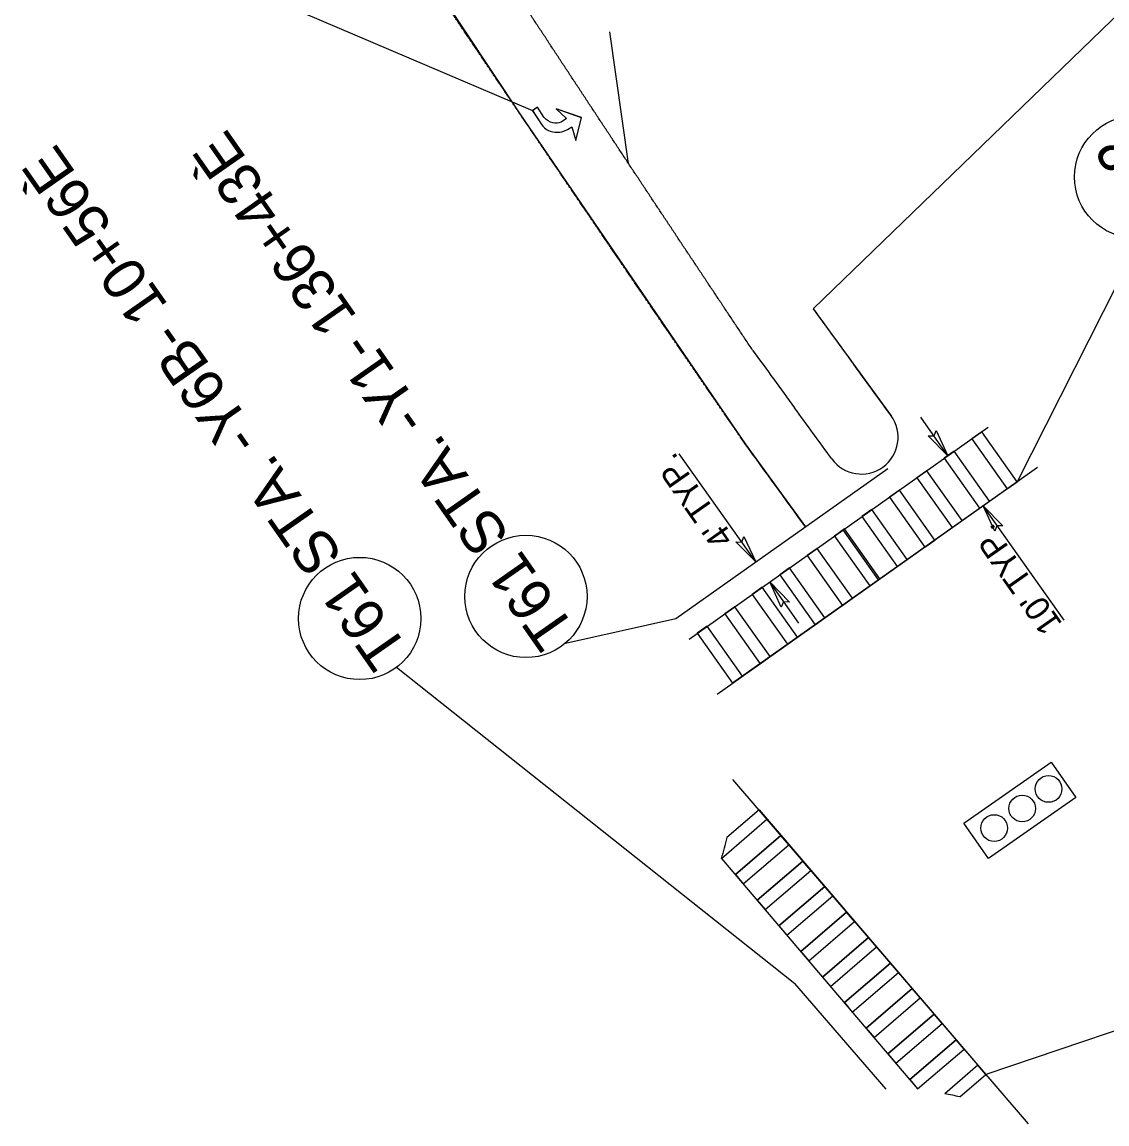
# Model space of a CAD drawing. Extents: x 1487421 to 1489048, y 497792 to 499463.
# Drawn here: x 1487578.8 to 1487756.3, y 498291.2 to 498471.4 of the extents above; entities that cross this region are included whole.
import ezdxf

# ---------------------------------------------------------------- set-up
doc = ezdxf.new("R2010")
doc.units = 0
for name, color, linetype in [('MARK LEFT TURN ARROW CELL', 7, 'Continuous'), ('Prop Dimension', 7, 'Continuous'), ('Prop Mkg Solid Double Yellow', 7, 'Continuous'), ('Prop Mkg Solid White Crosswalks', 7, 'Continuous'), ('Prop Mkg Solid White Lane Line', 7, 'Continuous'), ('Prop Mkg Solid White Stop Bar', 7, 'Continuous'), ('Prop Mkg Solid Yellow Diagonals', 7, 'Continuous'), ('Prop Mkr CR 80ft Spc', 7, 'Continuous'), ('Prop Mkr Yel 20ft Spc', 7, 'Continuous'), ('Prop PHM Traffic Signal CELL', 7, 'Continuous'), ('Scratch_Level_5', 7, 'Continuous'), ('Text', 7, 'Continuous')]:
    doc.layers.add(name, color=color, linetype=linetype)

msp = doc.modelspace()

# ---------------------------------------------------------------- linework, layer by layer
at = {"layer": 'MARK LEFT TURN ARROW CELL'}
for points in [[(1487663.15, 498457.49), (1487662.32, 498456.93), (1487663.75, 498454.78), (1487664.03, 498454.4), (1487664.29, 498454.13), (1487664.61, 498453.87), (1487664.94, 498453.69), (1487665.22, 498453.58), (1487665.64, 498453.46), (1487665.97, 498453.42), (1487666.35, 498453.39), (1487666.81, 498453.41), (1487667.14, 498453.47), (1487667.57, 498453.61), (1487668.09, 498453.86), (1487668.76, 498454.31), (1487669.45, 498452.07), (1487670.38, 498455.78), (1487666.23, 498457.23), (1487667.89, 498455.63), (1487667.33, 498455.26), (1487667.01, 498455.07), (1487666.67, 498454.96), (1487666.38, 498454.91), (1487665.97, 498454.89), (1487665.67, 498454.92), (1487665.27, 498455.05), (1487664.9, 498455.26), (1487664.57, 498455.49), (1487664.21, 498455.89)], [(1487663.15, 498457.49), (1487662.32, 498456.94), (1487663.75, 498454.78), (1487664.03, 498454.4), (1487664.29, 498454.13), (1487664.61, 498453.87), (1487664.94, 498453.69), (1487665.22, 498453.58), (1487665.64, 498453.46), (1487665.97, 498453.42), (1487666.35, 498453.39), (1487666.81, 498453.41), (1487667.14, 498453.48), (1487667.57, 498453.61), (1487668.09, 498453.86), (1487668.76, 498454.31), (1487669.45, 498452.07), (1487670.38, 498455.79), (1487666.23, 498457.23), (1487667.89, 498455.63), (1487667.33, 498455.26), (1487667.01, 498455.07), (1487666.67, 498454.96), (1487666.38, 498454.91), (1487665.97, 498454.89), (1487665.67, 498454.92), (1487665.27, 498455.05), (1487664.9, 498455.26), (1487664.57, 498455.5), (1487664.21, 498455.89)]]:
    msp.add_lwpolyline(points, close=True, dxfattribs=at)
at = {"layer": 'Prop Dimension'}
for p, q in [((1487730.29, 498400.5), (1487725.84, 498406.78)), ((1487698.85, 498383.13), (1487686.31, 498400.83)), ((1487749.33, 498373.6), (1487736.07, 498392.33)), ((1487705.92, 498373.14), (1487701.16, 498379.87))]:
    msp.add_line(p, q, dxfattribs=at)
for points in [[(1487728.37, 498404.64), (1487730.29, 498400.5), (1487727.06, 498403.76), (1487728.04, 498403.74)], [(1487737.95, 498388.17), (1487736.07, 498392.33), (1487739.27, 498389.03), (1487738.28, 498389.06)], [(1487696.92, 498387.27), (1487698.85, 498383.13), (1487695.61, 498386.4), (1487696.6, 498386.38)], [(1487703.04, 498375.71), (1487701.16, 498379.87), (1487704.36, 498376.57), (1487703.37, 498376.6)]]:
    msp.add_lwpolyline(points, close=True, dxfattribs=at)
at = {"layer": 'Prop Mkg Solid Double Yellow'}
for centre, radius, start, end in [((1494171.21, 503119.89), 7988.5, 215.998604, 216.079427), ((1494171.21, 503119.89), 8000.5, 215.996103, 216.079427), ((1479623.58, 492519.58), 10011.5, 36.020075, 36.079427), ((1479623.58, 492519.58), 9999.5, 36.020075, 36.079427), ((1487716.14, 498403.5), 6, 216.0201, 36.0201)]:
    msp.add_arc(centre, radius, start, end, dxfattribs=at)
msp.add_spline([(1487698.35, 498417.76), (1487697.82, 498418.54), (1487697.3, 498419.33), (1487696.77, 498420.12), (1487696.25, 498420.9), (1487695.72, 498421.69), (1487695.2, 498422.47), (1487694.68, 498423.26), (1487694.15, 498424.04), (1487693.63, 498424.83), (1487693.1, 498425.62), (1487692.58, 498426.4), (1487692.06, 498427.19), (1487691.53, 498427.97), (1487691.01, 498428.76), (1487690.49, 498429.55), (1487689.96, 498430.33), (1487689.44, 498431.12), (1487688.92, 498431.9), (1487688.39, 498432.69), (1487687.87, 498433.48), (1487687.35, 498434.26), (1487686.82, 498435.05), (1487686.3, 498435.84), (1487685.78, 498436.62), (1487685.26, 498437.41), (1487684.73, 498438.2), (1487684.21, 498438.98), (1487683.69, 498439.77), (1487683.17, 498440.56), (1487682.65, 498441.34), (1487682.12, 498442.13), (1487681.6, 498442.92), (1487681.08, 498443.71), (1487680.56, 498444.49), (1487680.04, 498445.28), (1487679.52, 498446.07), (1487678.99, 498446.86), (1487678.47, 498447.64), (1487677.95, 498448.43), (1487677.43, 498449.22), (1487676.91, 498450.01), (1487676.39, 498450.79), (1487675.87, 498451.58), (1487675.35, 498452.37), (1487674.83, 498453.16), (1487674.31, 498453.94), (1487673.79, 498454.73), (1487673.27, 498455.52), (1487672.75, 498456.31), (1487672.23, 498457.1), (1487671.71, 498457.88), (1487671.19, 498458.67), (1487670.67, 498459.46), (1487670.15, 498460.25), (1487669.63, 498461.04), (1487669.11, 498461.83), (1487668.59, 498462.62), (1487668.07, 498463.4), (1487667.55, 498464.19), (1487667.03, 498464.98), (1487666.51, 498465.77), (1487665.99, 498466.56), (1487665.47, 498467.35), (1487664.95, 498468.14), (1487664.44, 498468.93), (1487663.92, 498469.72), (1487663.4, 498470.5), (1487662.88, 498471.29), (1487662.36, 498472.08), (1487661.84, 498472.87), (1487661.33, 498473.66), (1487660.81, 498474.45), (1487660.29, 498475.24), (1487659.77, 498476.03)], degree=3, dxfattribs=at)
at = {"layer": 'Prop Mkg Solid White Crosswalks'}
for p, q in [((1487687.96, 498370.52), (1487736.9, 498405.17)), ((1487735.82, 498404.41), (1487734.19, 498403.25)), ((1487741.6, 498396.25), (1487735.82, 498404.41)), ((1487734.19, 498403.25), (1487739.97, 498395.09)), ((1487731.33, 498401.23), (1487729.7, 498400.08)), ((1487737.11, 498393.07), (1487731.33, 498401.23)), ((1487729.7, 498400.08), (1487735.48, 498391.91)), ((1487692.55, 498361.52), (1487744.93, 498398.61)), ((1487726.84, 498398.05), (1487725.21, 498396.9)), ((1487732.62, 498389.89), (1487726.84, 498398.05)), ((1487725.21, 498396.9), (1487730.99, 498388.74)), ((1487739.97, 498395.09), (1487741.6, 498396.25)), ((1487722.35, 498394.88), (1487720.72, 498393.72)), ((1487720.72, 498393.72), (1487726.5, 498385.56)), ((1487728.13, 498386.71), (1487722.35, 498394.88)), ((1487735.48, 498391.91), (1487737.11, 498393.07)), ((1487717.86, 498391.7), (1487716.23, 498390.54)), ((1487716.23, 498390.54), (1487722.01, 498382.38)), ((1487723.64, 498383.54), (1487717.86, 498391.7)), ((1487713.38, 498388.52), (1487711.74, 498387.36)), ((1487718.93, 498380.2), (1487713.16, 498388.36)), ((1487719.15, 498380.36), (1487713.38, 498388.52)), ((1487730.99, 498388.74), (1487732.62, 498389.89)), ((1487711.74, 498387.36), (1487717.52, 498379.2)), ((1487726.5, 498385.56), (1487728.13, 498386.71)), ((1487708.89, 498385.34), (1487707.25, 498384.18)), ((1487714.67, 498377.18), (1487708.89, 498385.34)), ((1487707.25, 498384.18), (1487713.03, 498376.02)), ((1487722.01, 498382.38), (1487723.64, 498383.54)), ((1487704.4, 498382.16), (1487702.77, 498381.01)), ((1487702.77, 498381.01), (1487708.55, 498372.84)), ((1487710.18, 498374), (1487704.4, 498382.16)), ((1487717.52, 498379.2), (1487719.15, 498380.36)), ((1487699.91, 498378.98), (1487698.28, 498377.83)), ((1487698.28, 498377.83), (1487704.06, 498369.67)), ((1487705.69, 498370.82), (1487699.91, 498378.98)), ((1487695.42, 498375.81), (1487693.79, 498374.65)), ((1487701.2, 498367.64), (1487695.42, 498375.81)), ((1487713.03, 498376.02), (1487714.67, 498377.18)), ((1487693.79, 498374.65), (1487699.57, 498366.49)), ((1487708.55, 498372.84), (1487710.18, 498374)), ((1487690.93, 498372.63), (1487689.3, 498371.47)), ((1487696.71, 498364.47), (1487690.93, 498372.63)), ((1487689.3, 498371.47), (1487695.08, 498363.31)), ((1487704.06, 498369.67), (1487705.69, 498370.82)), ((1487699.57, 498366.49), (1487701.2, 498367.64)), ((1487695.08, 498363.31), (1487696.71, 498364.47)), ((1487743.46, 498291.21), (1487695.12, 498347.53)), ((1487699.39, 498342.56), (1487694.15, 498338.06)), ((1487700.69, 498341.04), (1487699.39, 498342.56)), ((1487693.25, 498334.65), (1487700.69, 498341.04)), ((1487695.52, 498331.99), (1487702.97, 498338.38)), ((1487702.97, 498338.38), (1487695.52, 498331.99)), ((1487704.28, 498336.86), (1487702.97, 498338.38)), ((1487696.82, 498330.46), (1487704.28, 498336.86)), ((1487696.82, 498330.46), (1487704.28, 498336.86)), ((1487693.25, 498334.65), (1487725.34, 498296.96)), ((1487699.09, 498327.8), (1487706.56, 498334.21)), ((1487706.56, 498334.21), (1487699.09, 498327.8)), ((1487707.86, 498332.69), (1487706.56, 498334.21)), ((1487700.39, 498326.28), (1487707.86, 498332.69)), ((1487700.39, 498326.28), (1487707.86, 498332.69)), ((1487695.52, 498331.99), (1487696.82, 498330.46)), ((1487702.65, 498323.61), (1487710.14, 498330.03)), ((1487710.14, 498330.03), (1487702.65, 498323.61)), ((1487711.44, 498328.52), (1487710.14, 498330.03)), ((1487699.09, 498327.8), (1487700.39, 498326.28)), ((1487703.95, 498322.09), (1487711.44, 498328.52)), ((1487703.95, 498322.09), (1487711.44, 498328.52)), ((1487706.22, 498319.42), (1487713.72, 498325.86)), ((1487713.72, 498325.86), (1487706.22, 498319.42)), ((1487715.02, 498324.34), (1487713.72, 498325.86)), ((1487702.65, 498323.61), (1487703.95, 498322.09)), ((1487707.52, 498317.9), (1487715.02, 498324.34)), ((1487707.52, 498317.9), (1487715.02, 498324.34)), ((1487709.79, 498315.24), (1487717.3, 498321.69)), ((1487717.3, 498321.69), (1487709.79, 498315.24)), ((1487718.6, 498320.17), (1487717.3, 498321.69)), ((1487711.08, 498313.71), (1487718.6, 498320.17)), ((1487711.08, 498313.71), (1487718.6, 498320.17)), ((1487706.22, 498319.42), (1487707.52, 498317.9)), ((1487713.35, 498311.05), (1487720.88, 498317.51)), ((1487720.88, 498317.51), (1487713.35, 498311.05)), ((1487713.35, 498311.05), (1487720.88, 498317.51)), ((1487722.19, 498316), (1487720.88, 498317.51)), ((1487709.79, 498315.24), (1487711.08, 498313.71)), ((1487714.65, 498309.52), (1487722.19, 498316)), ((1487714.65, 498309.52), (1487722.19, 498316)), ((1487714.65, 498309.52), (1487722.19, 498316)), ((1487716.92, 498306.86), (1487724.47, 498313.34)), ((1487724.47, 498313.34), (1487716.92, 498306.86)), ((1487725.77, 498311.82), (1487724.47, 498313.34)), ((1487713.35, 498311.05), (1487714.65, 498309.52)), ((1487718.21, 498305.34), (1487725.77, 498311.82)), ((1487718.21, 498305.34), (1487725.77, 498311.82)), ((1487720.48, 498302.67), (1487728.05, 498309.17)), ((1487728.05, 498309.17), (1487720.48, 498302.67)), ((1487729.35, 498307.65), (1487728.05, 498309.17)), ((1487721.78, 498301.15), (1487729.35, 498307.65)), ((1487721.78, 498301.15), (1487729.35, 498307.65)), ((1487716.92, 498306.86), (1487718.21, 498305.34)), ((1487724.04, 498298.48), (1487731.63, 498304.99)), ((1487731.63, 498304.99), (1487724.04, 498298.48)), ((1487725.34, 498296.96), (1487732.93, 498303.47)), ((1487725.34, 498296.96), (1487732.93, 498303.47)), ((1487732.93, 498303.47), (1487731.63, 498304.99)), ((1487720.48, 498302.67), (1487721.78, 498301.15)), ((1487735.21, 498300.82), (1487729.78, 498296.16)), ((1487736.51, 498299.3), (1487735.21, 498300.82)), ((1487724.04, 498298.48), (1487725.34, 498296.96)), ((1487732.24, 498295.63), (1487736.51, 498299.3))]:
    msp.add_line(p, q, dxfattribs=at)
for centre, radius, start, end in [((1487653.13, 498347.05), 42, 342.8312, 347.6377), ((1487721.51, 498251.93), 45, 76.2084, 79.4045)]:
    msp.add_arc(centre, radius, start, end, dxfattribs=at)
at = {"layer": 'Prop Mkg Solid White Lane Line'}
msp.add_arc((1479623.58, 492519.58), 9989.5, 35.983189, 36.079401, dxfattribs=at)
for points in [[(1487660.29, 498456.42), (1487659.79, 498457.15), (1487659.3, 498457.88), (1487658.8, 498458.61), (1487658.31, 498459.34), (1487657.82, 498460.08), (1487657.32, 498460.81), (1487656.83, 498461.54), (1487656.33, 498462.27), (1487655.84, 498463), (1487655.35, 498463.73), (1487654.85, 498464.47), (1487654.36, 498465.2), (1487653.87, 498465.93), (1487653.37, 498466.66), (1487652.88, 498467.39), (1487652.39, 498468.12), (1487651.89, 498468.86), (1487651.4, 498469.59), (1487650.91, 498470.32), (1487650.41, 498471.05), (1487649.92, 498471.79), (1487649.43, 498472.52), (1487648.93, 498473.25), (1487648.44, 498473.98), (1487647.95, 498474.71), (1487647.46, 498475.45), (1487646.96, 498476.18), (1487646.47, 498476.91), (1487645.98, 498477.64), (1487645.49, 498478.38), (1487644.99, 498479.11), (1487644.5, 498479.84), (1487644.01, 498480.58), (1487643.52, 498481.31), (1487643.03, 498482.04), (1487642.54, 498482.77), (1487642.04, 498483.51), (1487641.55, 498484.24), (1487641.06, 498484.97), (1487640.57, 498485.71), (1487640.08, 498486.44), (1487639.59, 498487.17), (1487639.1, 498487.91), (1487638.61, 498488.64), (1487638.11, 498489.37), (1487637.91, 498489.68)], [(1487697.11, 498402.46), (1487696.61, 498403.18), (1487696.11, 498403.91), (1487695.61, 498404.64), (1487695.11, 498405.37), (1487694.61, 498406.09), (1487694.11, 498406.82), (1487693.61, 498407.55), (1487693.11, 498408.28), (1487692.61, 498409), (1487692.11, 498409.73), (1487691.61, 498410.46), (1487691.11, 498411.19), (1487690.61, 498411.92), (1487690.11, 498412.64), (1487689.61, 498413.37), (1487689.11, 498414.1), (1487688.61, 498414.83), (1487688.12, 498415.56), (1487687.62, 498416.28), (1487687.12, 498417.01), (1487686.62, 498417.74), (1487686.12, 498418.47), (1487685.62, 498419.2), (1487685.12, 498419.93), (1487684.62, 498420.66), (1487684.12, 498421.38), (1487683.63, 498422.11), (1487683.13, 498422.84), (1487682.63, 498423.57), (1487682.13, 498424.3), (1487681.63, 498425.03), (1487681.13, 498425.76), (1487680.64, 498426.49), (1487680.14, 498427.21), (1487679.64, 498427.94), (1487679.14, 498428.67), (1487678.65, 498429.4), (1487678.15, 498430.13), (1487677.65, 498430.86), (1487677.15, 498431.59), (1487676.66, 498432.32), (1487676.16, 498433.05), (1487675.66, 498433.78), (1487675.16, 498434.51), (1487674.67, 498435.24), (1487674.17, 498435.97), (1487673.67, 498436.7), (1487673.18, 498437.43), (1487672.68, 498438.16), (1487672.18, 498438.89), (1487671.69, 498439.62), (1487671.19, 498440.35), (1487670.69, 498441.08), (1487670.2, 498441.81), (1487669.7, 498442.54), (1487669.2, 498443.27), (1487668.71, 498444), (1487668.21, 498444.73), (1487667.72, 498445.46), (1487667.22, 498446.19), (1487666.73, 498446.92), (1487666.23, 498447.65), (1487665.73, 498448.38), (1487665.24, 498449.11), (1487664.74, 498449.84), (1487664.25, 498450.57), (1487663.75, 498451.3), (1487663.26, 498452.03), (1487662.76, 498452.76), (1487662.27, 498453.49), (1487661.77, 498454.23), (1487661.28, 498454.96), (1487660.78, 498455.69), (1487660.29, 498456.42)]]:
    msp.add_spline(points, degree=3, dxfattribs=at)
at = {"layer": 'Prop Mkg Solid White Stop Bar'}
for p, q in [((1487685.79, 498373.89), (1487720.45, 498398.43)), ((1487720.19, 498296.91), (1487705.27, 498314.2))]:
    msp.add_line(p, q, dxfattribs=at)
at = {"layer": 'Prop Mkg Solid Yellow Diagonals'}
msp.add_line((1487678.05, 498448.28), (1487674.99, 498469.81), dxfattribs=at)
at = {"layer": 'Prop Mkr CR 80ft Spc'}
msp.add_lwpolyline([(1487582.81, 498573.14), (1487660.29, 498456.42), (1487697.11, 498402.46), (1487706.98, 498388.89)], dxfattribs=at)
at = {"layer": 'Prop Mkr Yel 20ft Spc'}
msp.add_line((1487708.26, 498424.53), (1487720.99, 498407.03), dxfattribs=at)
for centre, radius, start, end in [((1494171.21, 503119.89), 8000.5, 215.996103, 216.079427), ((1479623.58, 492519.58), 9999.5, 36.020075, 36.079427), ((1487716.14, 498403.5), 6, 216.0201, 36.0201)]:
    msp.add_arc(centre, radius, start, end, dxfattribs=at)
msp.add_spline([(1487698.35, 498417.76), (1487697.82, 498418.54), (1487697.3, 498419.33), (1487696.77, 498420.12), (1487696.25, 498420.9), (1487695.72, 498421.69), (1487695.2, 498422.47), (1487694.68, 498423.26), (1487694.15, 498424.04), (1487693.63, 498424.83), (1487693.1, 498425.62), (1487692.58, 498426.4), (1487692.06, 498427.19), (1487691.53, 498427.97), (1487691.01, 498428.76), (1487690.49, 498429.55), (1487689.96, 498430.33), (1487689.44, 498431.12), (1487688.92, 498431.9), (1487688.39, 498432.69), (1487687.87, 498433.48), (1487687.35, 498434.26), (1487686.82, 498435.05), (1487686.3, 498435.84), (1487685.78, 498436.62), (1487685.26, 498437.41), (1487684.73, 498438.2), (1487684.21, 498438.98), (1487683.69, 498439.77), (1487683.17, 498440.56), (1487682.65, 498441.34), (1487682.12, 498442.13), (1487681.6, 498442.92), (1487681.08, 498443.71), (1487680.56, 498444.49), (1487680.04, 498445.28), (1487679.52, 498446.07), (1487678.99, 498446.86), (1487678.47, 498447.64), (1487677.95, 498448.43), (1487677.43, 498449.22), (1487676.91, 498450.01), (1487676.39, 498450.79), (1487675.87, 498451.58), (1487675.35, 498452.37), (1487674.83, 498453.16), (1487674.31, 498453.94), (1487673.79, 498454.73), (1487673.27, 498455.52), (1487672.75, 498456.31), (1487672.23, 498457.1), (1487671.71, 498457.88), (1487671.19, 498458.67), (1487670.67, 498459.46), (1487670.15, 498460.25), (1487669.63, 498461.04), (1487669.11, 498461.83), (1487668.59, 498462.62), (1487668.07, 498463.4), (1487667.55, 498464.19), (1487667.03, 498464.98), (1487666.51, 498465.77), (1487665.99, 498466.56), (1487665.47, 498467.35), (1487664.95, 498468.14), (1487664.44, 498468.93), (1487663.92, 498469.72), (1487663.4, 498470.5), (1487662.88, 498471.29), (1487662.36, 498472.08), (1487661.84, 498472.87), (1487661.33, 498473.66), (1487660.81, 498474.45), (1487660.29, 498475.24), (1487659.77, 498476.03)], degree=3, dxfattribs=at)
at = {"layer": 'Prop PHM Traffic Signal CELL'}
msp.add_lwpolyline([(1487736.91, 498334.62), (1487732.87, 498340.4), (1487747.17, 498350.4), (1487751.21, 498344.62)], close=True, dxfattribs=at)
for centre in [(1487746.75, 498346.01), (1487742.44, 498342.8), (1487737.86, 498339.6)]:
    msp.add_circle(centre, 2.19, dxfattribs=at)
at = {"layer": 'Scratch_Level_5'}
for p, q in [((1487741.6, 498396.25), (1487695.08, 498363.31)), ((1487699.39, 498342.56), (1487736.51, 498299.3))]:
    msp.add_line(p, q, dxfattribs=at)
at = {"layer": 'Text'}
for p, q in [((1487603.98, 498481.86), (1487662.32, 498456.94)), ((1487764.84, 498479.24), (1487708.26, 498424.53)), ((1487761.79, 498436.13), (1487741.6, 498396.25)), ((1487667.73, 498369.84), (1487685.8, 498373.88)), ((1487640.11, 498365.92), (1487705.27, 498314.2)), ((1487837.42, 498333.39), (1487736.51, 498299.3))]:
    msp.add_line(p, q, dxfattribs=at)
for centre in [(1487760.99, 498446.09), (1487661.26, 498377.48), (1487634.07, 498373.88)]:
    msp.add_circle(centre, 10, dxfattribs=at)

# ---------------------------------------------------------------- texts
at = {"layer": 'Prop Dimension'}
for s, p in [("4' TYP.", (1487695.4, 498387.07)), ("10' TYP.", (1487749.12, 498373.01))]:
    msp.add_text(s, height=4, rotation=125.0335, dxfattribs=at).set_placement(p)
at = {"layer": 'Text'}
for s, p in [('T61 STA. -Y1- 136+43È', (1487669.54, 498372.05)), ('T62', (1487768.9, 498441.11)), ('T61 STA. -Y6B- 10+56È', (1487642.22, 498368.78))]:
    msp.add_text(s, height=7, rotation=124.9556, dxfattribs=at).set_placement(p)

doc.saveas('drawing.dxf')
